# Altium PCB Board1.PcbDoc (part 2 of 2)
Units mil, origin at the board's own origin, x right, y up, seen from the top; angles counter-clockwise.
Board outline 6000 x 4000 mil, 8 copper layers (Top Layer, 3.3V, 2.5V, 1.8V, 1.0V, GND, signal2, Bottom Layer), stack 66.302 mil thick; 90 components, 131 nets, 720 pads, 306 vias.
Unrouted connection lines stored in the file: 162.
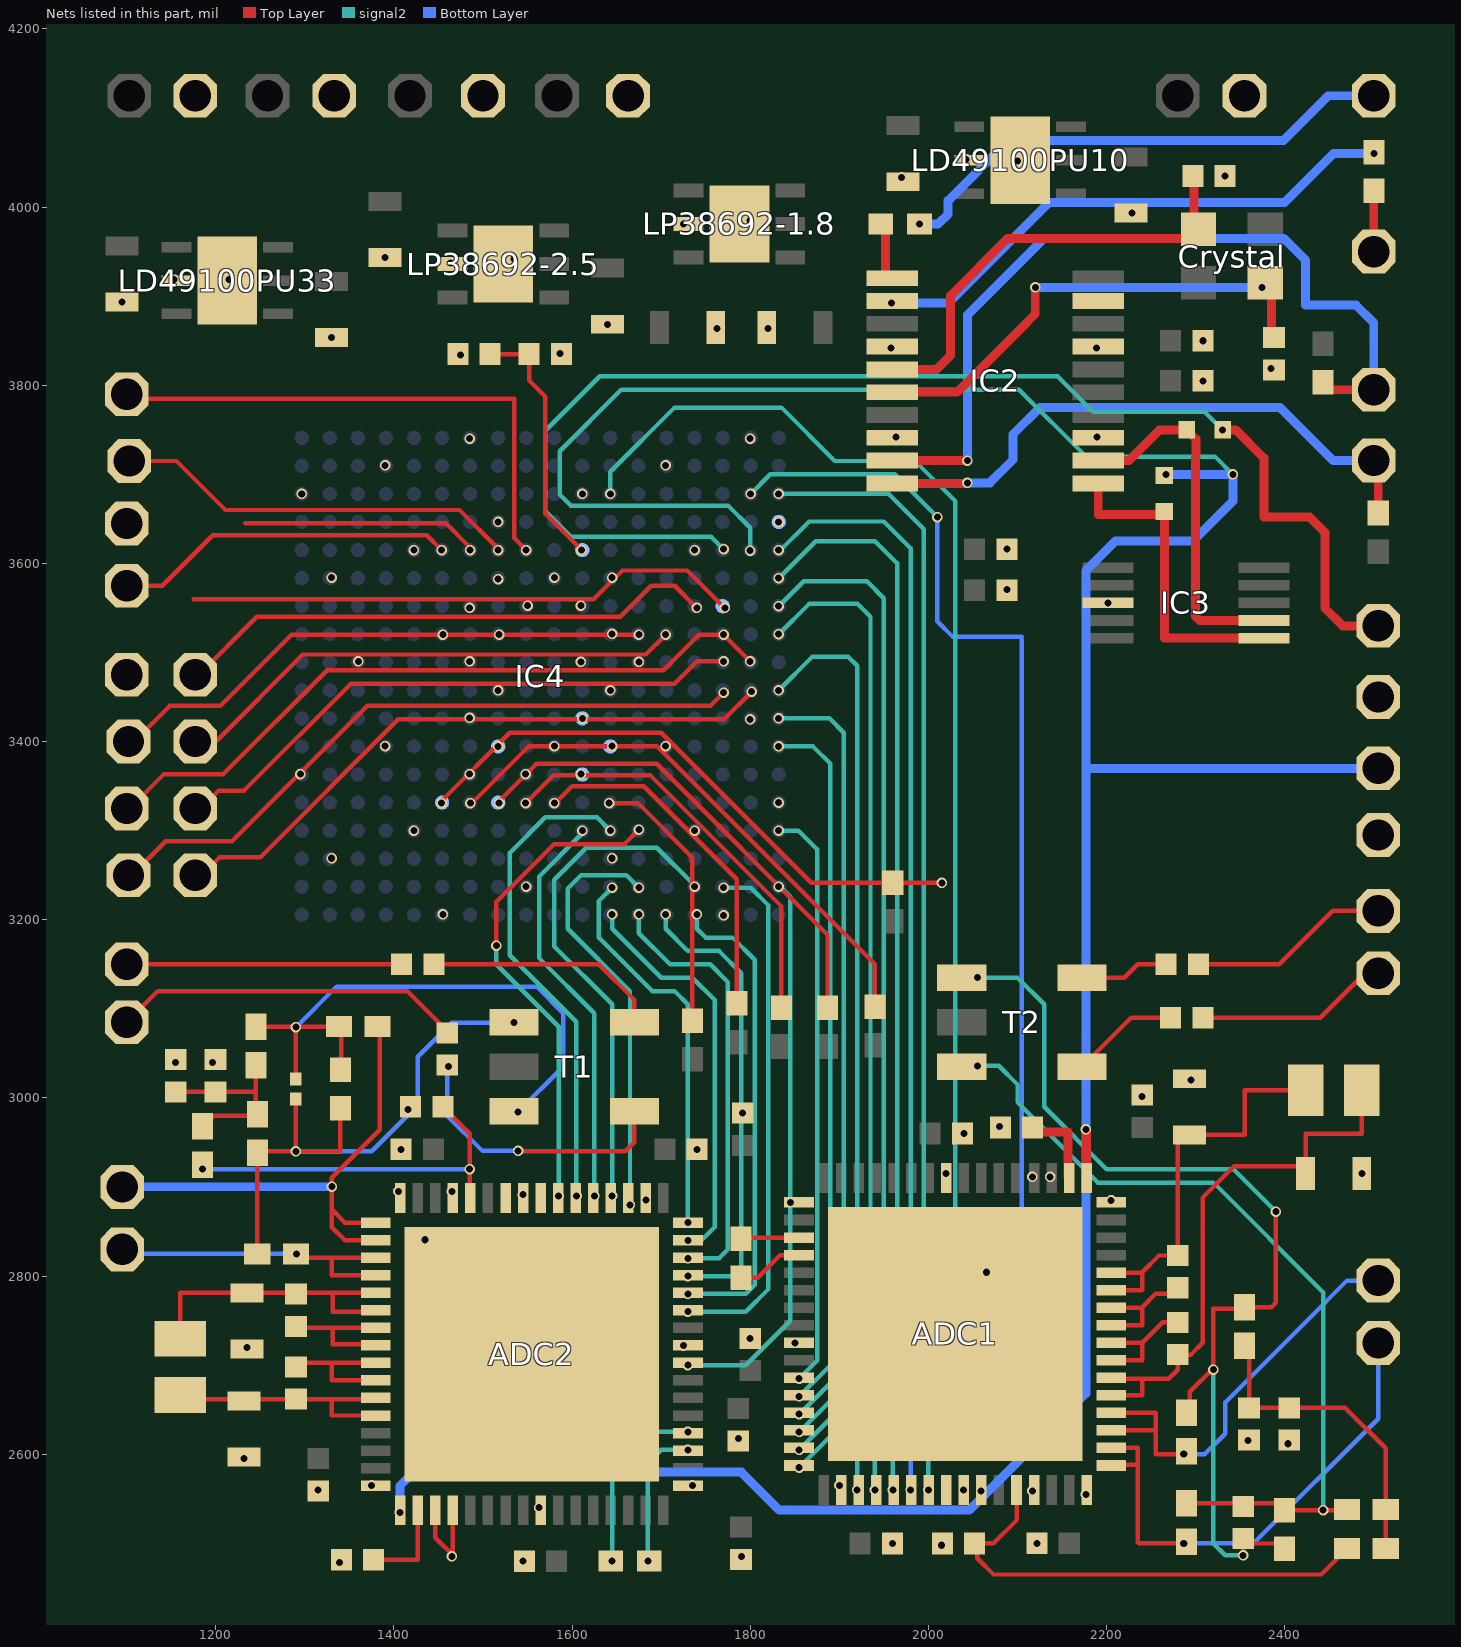
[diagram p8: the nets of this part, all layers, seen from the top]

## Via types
v1: diameter 11.81, hole 7.87, Top Layer to GND, 77 vias
v2: diameter 11.81, hole 7.87, Top Layer to Bottom Layer, 50 vias
v3: diameter 11.81, hole 7.87, GND to Bottom Layer, 47 vias
v4: diameter 11.81, hole 7.87, Top Layer to signal2, 33 vias
v5: diameter 11.81, hole 7.87, 3.3V to Bottom Layer, 27 vias
v6: diameter 11.81, hole 7.87, signal2 to Bottom Layer, 25 vias
v7: diameter 11.81, hole 7.87, Top Layer to 2.5V, 17 vias
v8: diameter 11.81, hole 7.87, 1.0V to Bottom Layer, 16 vias
v9: diameter 11.81, hole 7.87, Top Layer to 3.3V, 10 vias
v10: diameter 11.81, hole 7.87, 1.8V to Bottom Layer, 4 vias

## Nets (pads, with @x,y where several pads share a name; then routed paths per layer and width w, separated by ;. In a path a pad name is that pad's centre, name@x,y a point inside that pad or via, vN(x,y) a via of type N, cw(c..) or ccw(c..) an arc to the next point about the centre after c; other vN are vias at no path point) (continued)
ADC1_1: ADC1.43 | length 654.1
  signal2 w5: v6(1831.97,3300.08) 1854.09,3300.08 1875,3279.17 1875,2705 v4(1855,2685)
ADC1_2: ADC1.44 | length 790.6
  signal2 w5: v6(1831.97,3394.57) 1870.43,3394.57 1890,3375 1890,2700 v4(1855,2665)
ADC1_3: ADC1.45 | length 865.4
  signal2 w5: v6(1831.97,3426.06) 1888.94,3426.06 1905,3410 1905,2695 v4(1855,2645)
ADC1_4: ADC1.46 | length 994.6
  signal2 w5: v6(1831.97,3457.56) 1869.41,3495 1910,3495 1920,3485 1920,2690 v4(1855,2625)
ADC1_5: ADC1.47 | length 1091.7
  signal2 w5: v6(1831.97,3520.55) 1866.42,3555 1920,3555 1935,3540 1935,2685 v4(1855,2605)
ADC1_6: ADC1.48 | length 1152.8
  signal2 w5: v6(1831.97,3552.05) 1859.92,3580 1930.98,3580 1950,3560.98 1950,2680 v4(1855,2585)
ADC1_7: ADC1.51 | length 1219.2
  signal2 w5: v6(1831.97,3583.54) 1873.43,3625 1940,3625 1965,3600 1965,2675 1920,2630 v4(1920,2560)
ADC1_8: ADC1.52 | length 1247.4
  signal2 w5: v6(1831.97,3615.04) 1834.06,3615.04 1866.1,3647.09 1950,3647.09 1980,3617.09 1980,2670 1940,2630 v4(1940,2560)
ADC1_9: ADC1.53 | length 1272.4
  signal2 w5: v6(1831.97,3678.03) 1955.47,3678.03 1995,3638.5 1995,2665 1960,2630 v4(1960,2560)
ADC1_10: ADC1.54 | length 1464.6
  signal2 w5: v6(1800.47,3678.03) 1822.44,3700 1962.09,3700 v2(2010,3652.09)
  Bottom Layer w5: v2(1980,2560) 1980,2620 2105,2745 2105,3515 ; v2(2010,3652.09) 2010,3535 2027.52,3517.48 2105,3517.48
ADC1_11: ADC1.55 | length 1607.7
  signal2 w5: v6(1642.99,3678.03) 1642.99,3702.99 1715,3775 1835,3775 1895,3715 1985,3715 2030,3670 2030,2645 2000,2615 v4(2000,2560)
ADC2_0: ADC2.40 | length 629.3
  signal2 w5: v4(1730,2700) 1795,2700 1845,2750 1845,3225.98 1833.9,3237.09 v6(1831.97,3237.09)
ADC2_1: ADC2.43 | length 590
  signal2 w5: v4(1730,2760) 1795,2760 1820,2785 1820,3216.57 1800.59,3235.98 v6(1770,3235.98)
ADC2_2: ADC2.44 | length 539.7
  signal2 w5: v4(1730,2780) 1795,2780 1805,2790 1805,3155 1780,3180 1750,3180 1740,3190 v6(1740,3206.06)
ADC2_3: ADC2.45 | length 518.7
  signal2 w5: v6(1705,3206.06) 1705,3190 1730,3165 1765,3165 1790,3140 1790,2804.65 1785.35,2800 ; v4(1730,2800) 1785,2800
ADC2_4: ADC2.46 | length 493
  signal2 w5: v6(1675,3206.06) 1675,3185 1710,3150 1755,3150 1775,3130 1775,2830 1765,2820 v4(1730,2820)
ADC2_5: ADC2.47 | length 455.4
  signal2 w5: v6(1645,3206.06) 1645,3190 1700,3135 1735,3135 1760,3110 1760,2855 1745,2840 v4(1730,2840)
ADC2_6: ADC2.48 | length 438.3
  signal2 w5: v6(1645,3236.06) 1630,3221.06 1630,3180 1690,3120 1715,3120 1730,3105 v4(1730,2860)
ADC2_7: ADC2.51 | length 476
  signal2 w5: v4(1665,2880) 1665,3120 1595,3190 1595,3235 1610,3250 1661.06,3250 v6(1675,3236.06)
ADC2_8: ADC2.52 | length 573.4
  signal2 w5: v4(1645,2890) 1645,3105 1580,3170 1580,3245 1615.98,3280.98 1695.08,3280.98 1737.48,3238.58 v6(1737.48,3237.09)
ADC2_9: ADC2.53 | length 455.9
  signal2 w5: v6(1611.5,3300.08) 1611.5,3296.97 1562.95,3248.43 1562.95,3157.05 1625,3095 v4(1625,2890)
ADC2_10: ADC2.54 | length 554.6
  signal2 w5: v4@1604.53,2890 1604.53,3085.47 1530,3160 1530,3275 1570,3315 1628.07,3315 v6(1642.99,3300.08) v6@1642.99,3303.07
  other v4: 1605,2890
ADC2_11: ADC2.55 | length 552.6
  Top Layer w5: v2(1515,3171.06) 1515,3220 1580,3285 1658.94,3285 v2(1675,3301.06)
  signal2 w5: v2(1515,3171.06) 1515,3150 1585,3080 v4(1585,2890)
C1_1: C1.1 T2.5 | length 126
  Top Layer w5: T2.5@2172.52,3035 2227.52,3090 C1.1@2275.77,3090
C1_2: C1.2 pad.0@2505,3140 | length 202.6
  Top Layer w5: C1.2@2308.11,3090 2440,3090 pad.0@2490,3140
C2_1: C2.1 T2.4 | length 93.1
  Top Layer w5: T2.4@2185,3135 2220,3135 2235,3150 C2.1@2271.89,3150
C2_2: 
C65_1: ADC1.60 C65.1@2051.89,2499.8 R_new2.2 | length 530.5
  Top Layer w5: ADC1.60@2099.37,2550 2099.37,2526.26 2073.11,2500 2054.92,2500 2054.92,2483.19 2073.11,2465 2440.98,2465 R_new2.2@2469.96,2493.98
Clock1: ADC1.17 ADC2.17 pad.0@2505,3370 R32.2 | length 3609.8
  Top Layer w10: ADC1.17@2177.64,2910.2 v2@2177.64,2961.89
  signal2 w5: v6(1800,3614.49) 1800,3640.08 1775.08,3665 1598.5,3665 1586.06,3677.44 1586.06,3726.06 1655,3795 2101.81,3795 2176.81,3720 2321.73,3720 v2(2341.81,3699.92)
  Bottom Layer w10: v2(1406.81,2534.76) 1406.81,2564.41 1422.4,2580 1790,2580 1832.72,2537.28 2045.91,2537.28 2176.81,2668.19 v2(2176.81,2964.76) 2176.81,3370 ; v2(2266.81,3699.92) v2(2341.81,3699.92) 2341.81,3670 2300,3628.19 ; 2300,3625 2210,3625 2176.81,3591.81 2176.81,3370 ; pad.0@2505,3370 2176.81,3370
Clock2: pad.0@2505,3530 R31.2 | length 1472.8
  Top Layer w10: R31.2@2330.32,3750 2345,3750 2376.65,3718.35 2376.65,3652.09 2427.91,3652.09 2445,3635 2445,3550 2465,3530 pad.0@2505,3530
  signal2 w5: v6(1770,3615.98) 1755.98,3630 1598.5,3630 1570,3658.5 1570,3748.94 1631.06,3810 2145,3810 2185,3770 2310.08,3770 v2(2330.16,3749.92)
DONE: R41.2 | length 475.1
  Top Layer w5: v2@1547.95,3331.06 1579.37,3362.48 1687.52,3362.48 1835,3215 R41.2@1835,3101.05
  other v2: 1547.95,3330.98
GND: ADC1.16 ADC1.25 ADC1.33 ADC1.41 ADC1.50 ADC1.57 ADC1.58 ADC1.61 ADC1.64 ADC1.65 ADC2.16 ADC2.19 ADC2.20 ADC2.25 ADC2.33 ADC2.41 ADC2.50 ADC2.57 ADC2.58 ADC2.61 ADC2.64 ADC2.65 C2.2 C3.1 C4.1 C7.1 C8.2 C17.1 C18.1 C19.2 C20.1 C21.1 C22.1 C24.1 C25.1 C26.1 C29.1 C31.2 C33.1 C39.1 C40.1 C41.2 C42.1 C43.1 C48.2 C50.2 C52.1 C53.1 C54.1 C56.2 C57.1@1971.5,4028.5 C58.1 C59.1 C60.1 C61.1 C62.1 C63.2 C64.1 C65.1@1471.89,3835 C65.2@2015.67,2499.8 C66.1@1418.78,2990 C66.2@1588.11,3835 C67.1 C68.2 IC2.4 IC2.8 IC2.13 IC2.17 IC3.8 IC4.D1 IC4.L8 IC4.M7 IC4.M11 IC4.N8 LD49100PU10.2 LD49100PU10.7 LD49100PU33.2 LD49100PU33.7 LP38692-1.8.2 LP38692-1.8.7 LP38692-2.5.2 LP38692-2.5.7 pad.0@1100,3150 pad.0@1177.05,4125 pad.0@1332.95,4125 pad.0@1500,4125 pad.0@1662.95,4125 pad.0@2355,4125 pad.0@2505,3210 pad.0@2505,3295 pad.0@2505,3450 | length 643.5
  Top Layer w5: pad.0@1100,3150 C24.1@1407.17,3150 ; ADC2.19@1446.54,2537.17 1446.54,2506.14 1466.22,2486.46 ADC2.20@1466.22,2537.17 ; C2.2@2303.11,3150 2393.94,3150 2453.94,3210 pad.0@2505,3210
  other v1: 1339.13,2478.35 1545,2480 1465,2485.24 1790,2485 2014.65,2497.83 1959.53,2499.8 2121.89,2500 1562.95,2540 2176.81,2555 2059.21,2558.86 2116.78,2558.86 1315,2560 2039.53,2559.84 1375,2565 1735,2565 1900,2565 1231.73,2595 2403.74,2611.77 2358.74,2615.55 1786.57,2617.91 1235,2719.68 1725,2721.89 1850,2725 1800,2730 2065,2804.3 1435,2840.79 1845,2882.64 1682.91,2885.47 2205,2885 1544.65,2891.5 1405,2895 1465,2895 2116.78,2911.38 2136.78,2911.38 2020,2915 2486.5,2915 1407.99,2942.36 1740.43,2942.36 2040,2960 2080,2968.07 1791.57,2982.87 1415.63,2986.89 2240,3001.69 2295,3020 1155,3040 1196.5,3040 2015,3241.5 2201.46,3555.63 2088.11,3570.98 2088.11,3615.98 1963.74,3741.89 2189.39,3741.89 2308.11,3805 2384.8,3818.78 1475,3833.94 1586.5,3835.69 1957.76,3841.89 2188.74,3841.89 2308.11,3850 1330,3853.5 1762.91,3863.5 1820,3863.5 1640,3868.5 1095,3893.5 1153.39,3918.5 1215,3918.5 1463.5,3937.01 1535,3942.01 1389.96,3943.5 1725,3981.1 1800,3985 2228.62,3993.5 1970,4033.5 2333.11,4035 2100,4052.01 2042.48,4053.5
  other v3: 1770,3205 1455,3206.06 1548.5,3237.09 1330,3269.06 1645,3269.06 1422.52,3300.08 1737.48,3300.08 1831.97,3331.57 1295,3363.54 1485,3363.54 1547.95,3363.54 1610,3363.54 1390,3395 1517.01,3394.57 1580,3395 1645,3395.04 1705,3395 1800,3425 1611.5,3426.06 1485,3426.54 1517.01,3457.56 1642.99,3457.56 1360,3490 1485,3490 1610,3489.53 1675,3489.53 1455,3520 1518.03,3520 1770,3520 1645,3521.02 1485,3550 1550,3552.52 1610,3552.52 1517.01,3582.52 1330,3584.02 1580,3584.02 1645,3584.02 1422.52,3615.04 1737.48,3615.04 1517.01,3646.54 1831.97,3646.54 1296.54,3678.03 1611.5,3678.03 1390,3710 1705,3710 1485,3740 1800,3740
INIT: R39.2 | length 302.1
  Top Layer w5: v2(1641.5,3330.98) 1674.02,3330.98 1735,3270 R39.2@1735,3086.65
IO1: IC4.G3 pad.0@1100,3475 | length 627.3
  Top Layer w5: 1175,3560 1624.41,3560 1656.5,3592.09 1729.45,3592.09 v2(1771.54,3550)
IO2: pad.0@1177.05,3475 | length 612
  Top Layer w5: pad.0@1180,3473.98 1246.02,3540 1653.98,3540 1688.78,3574.8 1715.2,3574.8 v2(1740,3550)
IO3: pad.0@1102.05,3400 | length 628.2
  Top Layer w5: pad.0@1100,3391.61 1148.39,3440 1205,3440 1285,3520 v2(1675,3520)
IO4: pad.0@1177.05,3400 | length 569
  Top Layer w5: pad.0@1185,3401.61 1201.61,3401.61 1297.8,3497.8 1682.8,3497.8 v2(1705,3520)
IO5: pad.0@1100,3325 | length 787.5
  Top Layer w5: pad.0@1105,3326.61 1141.93,3363.54 1208.54,3363.54 1325,3480 1702.52,3480 1742.52,3520 1770,3520 v2(1800,3490)
IO6: pad.0@1177.05,3325 | length 659.7
  Top Layer w5: pad.0@1180,3321.61 1203.39,3345 1231.73,3345 1351.73,3465 1715,3465 1740,3490 v2(1770,3490)
IO7: pad.0@1102.05,3250 | length 744.5
  Top Layer w5: pad.0@1108.98,3253.39 1143.82,3288.23 1218.23,3288.23 1370,3440 1755,3440 v2(1770,3455)
IO8: pad.0@1177.05,3250 | length 712.2
  Top Layer w5: pad.0@1177.48,3243.39 1204.09,3270 1250,3270 1405,3425 1770.59,3425 v2(1801.57,3455.98)
M0: R43.2 | length 627.9
  Top Layer w5: v2@1487.56,3330.98 1551.57,3395 1695,3395 1940,3150 R43.2@1940,3102.55
  other v2: 1485.91,3330.98
M1: IC4.P13 R44.2 | length 664.8
  Top Layer w5: v2@1452.24,3332.24 1530,3410 1700,3410 1868.5,3241.5 R44.2@1960,3241.5 2015,3241.5
  other v2: 1453.5,3330.98
M2: IC4.P11 R42.2 | length 547.7
  Top Layer w5: v2@1518.03,3333.03 1560,3375 1695,3375 1886.73,3183.27 R42.2@1886.73,3101.05
  other v2: 1518.03,3330.98
NetADC1_1: ADC1.1 ADC1.2 pad.0@2505,2725 R6.2 | length 584.1
  Top Layer w5: ADC1.2@2205.2,2607.05 2235,2607.05 2235,2588.35 ; ADC1.1@2206.18,2588.35 2235,2588.35 ; 2235,2501.34 2235,2588.35 ; 2236.28,2500.06 R6.2@2290,2500.06
  Top Layer w10: v2(2286.65,2500) R6.2@2290,2503.35
  Bottom Layer w5: v2(2286.65,2500) 2365,2500 2505,2640 pad.0@2505,2725
NetADC1_3: ADC1.3 ADC1.4 pad.0@2505,2795 R7.2 | length 497.1
  Top Layer w5: ADC1.3@2205.2,2626.73 2255,2626.73 ; ADC1.4@2205.2,2646.42 2254.76,2646.42 ; 2255,2646.42 2255,2600 v2(2286.65,2600)
  Bottom Layer w5: v2(2286.65,2600) 2310,2600 2333.11,2623.11 2333.11,2658.11 2425,2750 2470,2795 pad.0@2505,2795
NetADC1_5: ADC1.5 ADC1.6 C5.2 C7.2 C9.2 | length 623.5
  Top Layer w5: ADC1.5@2205.2,2666.1 2240,2666.1 2240,2684.76 ADC1.6@2206.22,2684.76 ; 2239.53,2684.76 2269.76,2684.76 2280,2695 C5.2@2280,2711.89 2294.83,2711.89 2308.1,2725.16 2308.1,2888.1 2343.5,2923.5 2423.5,2923.5 2423.5,2960 2486.5,2960 C9.2@2486.5,3008.54
NetADC1_7: ADC1.7 ADC1.8 C5.1 | length 138.6
  Top Layer w5: ADC1.7@2205.2,2705.47 2240,2705.47 2240,2725.16 ADC1.8@2205.2,2725.16 ; 2240.16,2725.16 2263.11,2748.11 C5.1@2280,2748.11
NetADC1_9: ADC1.9 ADC1.10 C6.2 | length 129.2
  Top Layer w5: ADC1.9@2205.2,2744.84 2239.84,2744.84 ; ADC1.10@2205.2,2764.53 2239.53,2764.53 ; 2240,2745 2240,2764.06 ; 2240,2765 2255,2780 C6.2@2275,2780
NetADC1_11: ADC1.11 ADC1.12 C6.1 C8.1 C9.1 | length 458.5
  Top Layer w5: ADC1.11@2205.2,2784.21 2239.68,2784.21 ; ADC1.12@2205.2,2803.9 2239.84,2803.9 2239.84,2784.37 ; 2240,2804.3 2258.81,2823.11 C6.1@2280,2823.11 C8.1@2280,2965 ; C8.1@2293.35,2958.5 2355,2958.5 2355,3008.54 C9.1@2423.5,3008.54
NetADC1_13: 
NetADC1_17: 
NetADC1_18: ADC1.18 C67.2 | length 87.1
  Top Layer w10: C67.2@2119.61,2961.89 2156.5,2961.89 ADC1.18@2156.5,2911.65
NetADC1_55: 
NetADC1_56: ADC1.56
NetADC2_1: ADC2.1 ADC2.2 pad.0@1095,2900 R17.2 | length 614.1
  Top Layer w5: ADC2.2@1379.61,2840.32 1345.32,2839.98 1330.29,2854.72 ; ADC2.1@1379.61,2860 1345,2860 1330.1,2874.9 1330.29,2854.72 ; R17.2@1384.13,3080 1384.13,2964.13 1330.29,2910.29 v2(1330.29,2900.29) 1330.29,2854.72
  Bottom Layer w10: pad.0@1095,2900 v2(1330.29,2900.29)
NetADC2_3: ADC2.3 ADC2.4 pad.0@1095,2830 R18.2 | length 344.8
  Top Layer w5: R18.2@1294.37,2820.63 ADC2.3@1379.61,2820.63 ; 1330,2820.63 1330,2801.14 ADC2.4@1379.41,2801.14
  Bottom Layer w5: pad.0@1100,2825 v2(1290.63,2825)
NetADC2_5: ADC2.5 ADC2.6 C28.2 C29.2 C30.2 | length 339.3
  Top Layer w5: C28.2@1160,2729.61 1160,2781.26 ADC2.5@1379.61,2781.26 ; 1331.26,2781.26 1331.26,2760 ADC2.6@1378.03,2760
NetADC2_7: ADC2.7 ADC2.8 C30.1 | length 155.5
  Top Layer w5: C30.1@1290,2741.89 ADC2.7@1379.61,2741.89 ; 1331.26,2741.89 1331.26,2723.27 ADC2.8@1378.54,2723.27
NetADC2_9: ADC2.9 ADC2.10 C32.2 | length 154.5
  Top Layer w5: C32.2@1294.41,2702.52 ADC2.9@1379.61,2702.52 ; 1330,2702.52 1330,2682.83 ADC2.10@1379.61,2682.83
NetADC2_11: ADC2.11 ADC2.12 C28.1 C31.1 C32.1 | length 274.5
  Top Layer w5: C28.1@1171.89,2661.89 C32.1@1290,2661.89 ADC2.11@1378.35,2661.89 ; 1330,2661.89 1330,2643.46 ADC2.12@1379.61,2643.46
NetADC2_17: 
NetADC2_18: ADC2.18 C68.1 | length 105.3
  Top Layer w5: C68.1@1377.24,2481.46 1426.85,2481.46 ADC2.18@1426.85,2537.17
NetADC2_55: 
NetADC2_56: ADC2.56
NetC1_2: 
NetC2_1: 
NetC2_2: 
NetC3_1: 
NetC3_2: C3.2 C4.2 R1.1 R2.2 R_new2.1 | length 351.6
  Top Layer w5: R2.2@2360,2718.78 C4.2@2360,2651.97 2468.03,2651.97 2513.27,2606.73 R_new2.1@2513.27,2493.98
NetC10_1: 
NetC11_2: 
NetC12_2: 
NetC13_1: C13.1 R2.1 R5.1 R7.1 T2.3 | length 1114.7
  Top Layer w5: R7.1@2293.35,2650 2293.35,2670.01 2320,2696.66 2320,2763.11 R2.1@2352.99,2763.11 ; v4(2353.35,2486.46) C13.1@2353.35,2505.16 ; R2.1@2355,2765.12 2385.12,2765.12 2390,2770 v4(2390,2872.4) ; C13.1@2360,2499.8 2405.82,2499.8 R5.1@2400,2493.98
  signal2 w5: v4(2055,3135) 2100,3135 2130,3105 2130,2990 2200,2920 2342.4,2920 v4(2390,2872.4) ; v4(2320,2695) 2320,2499.57 2333.11,2486.46 v4(2353.35,2486.46)
NetC13_2: C13.2 R1.2 R5.2 R6.1 T2.1 | length 925.8
  Top Layer w5: R6.1@2290.86,2544.93 2392.36,2544.93 R5.2@2399.17,2538.11 ; R5.2@2400,2537.28 R1.2@2465,2537.28
  signal2 w5: v4(2055,3036.02) 2078.98,3036.02 2100,3015 2100,2995 2190,2905 2320,2905 2443.03,2781.97 v4(2443.03,2537.28)
NetC14_1: 
NetC14_2: 
NetC15_2: 
NetC23_1: C23.2 pad.0@1100,3085 | length 391
  Top Layer w5: pad.0@1100,3085 1135,3120 1415,3120 C23.2@1458.5,3076.5
NetC23_2: C23.1 T1.5 | length 320.3
  Top Layer w5: v2@1539.4,2940 1659.61,2940 1670,2950.39 T1.5@1670,2985
  Bottom Layer w5: v2@1460,3035 1460,2980 1499.54,2940.46 v2(1539.4,2940.46)
  other v2: 1461.45,3035.46
NetC24_1: 
NetC24_2: C24.2 T1.4 | length 266.6
  Top Layer w5: C24.2@1444.96,3150 1630,3150 1670,3110 T1.4@1670,3085
NetC25_2: C25.2 C26.2 R14.1 R15.2 R_new1.2 | length 208.2
  Top Layer w5: C26.2@1155,3006.89 1243.11,3006.89 ; R_new1.2@1186.42,2968.31 1198.11,2980 1245,2980 R14.1@1245,3036.69
NetC27_1: 
NetC34_2: 
NetC35_2: 
NetC36_1: 
NetC36_2: 
NetC37_2: 
NetC44_2: 
NetC47_2: 
NetC48_2: 
NetC52_2: C52.2 Crystal.1@2303.11,3975 IC2.5 | length 512.9
  Top Layer w10: IC2.5@1959.33,3817.8 2009.29,3817.8 2025,3833.5 2025,3900.71 2089.29,3965 Crystal.1@2308.11,3965 ; Crystal.1@2298.11,3970 C52.2@2298.11,4033.78
NetC53_2: C53.2 Crystal.1@2378.11,3915 IC2.6 | length 527.8
  Top Layer w10: IC2.6@1959.33,3792.2 2032.2,3792.2 2101.75,3861.75 2120,3880 v2(2120,3910) ; C53.2@2385,3853.5 Crystal.1@2385,3899.25
  Bottom Layer w10: v2(2120,3910) v2@2375,3910
  other v2: 2374.33,3909.92
NetC57_1: C57.1@1290,2998.9 R15.1 R16.1 R18.1 T1.3 | length 651.3
  Top Layer w5: R18.1@1246.69,2825 R15.1@1246.69,2938.35 1248.35,2940 1340,2940 R16.1@1340,2988.35 ; v2(1290,2940) C57.1@1290,2998.9
  Bottom Layer w5: v2(1290,2940) 1375,2940 1426.85,2991.85 1426.85,3046.25 1465,3084.4 v2(1535,3084.4)
NetC57_2: C57.2@1290,3021.1 R14.2 R16.2 R17.1 T1.1 | length 662.6
  Top Layer w5: R14.2@1245,3080 R17.1@1338.35,3080 ; C57.2@1290,3021.1 v2@1290,3080 ; R16.2@1340.83,3032.48 R17.1@1340.83,3080
  Bottom Layer w5: v2(1290,3079.4) 1335.6,3125 1560,3125 1590,3095 1590,3035 v2(1539.4,2984.4)
NetC66_2: ADC2.60 C66.2@1455,2990 R_new1.1 | length 414
  Top Layer w5: C66.2@1455,2990 1485,2960 ADC2.60@1485,2888.46
  Bottom Layer w5: v2(1185,2920) v2(1485,2920)
NetIC1_3: 
NetIC1_8: 
NetIC2_1: 
NetIC2_2: 
NetIC2_6: 
NetIC2_11: IC2.11 IC3.1 R32.1 | length 349.4
  Top Layer w10: IC2.11@2190.67,3689.84 2190.67,3655 R32.1@2259.76,3655 ; R32.1@2264.84,3649.92 2264.84,3516.26 IC3.1@2376.65,3516.26
NetIC2_12: IC2.12 IC3.2 R31.1 | length 405.1
  Top Layer w10: IC2.12@2190.67,3715.43 2225,3715.43 2259.57,3750 R31.1@2290,3750 2300.32,3739.68 2300.32,3720 ; 2300,3540.63 2300,3719.68 ; 2300.32,3540.32 2304.69,3535.94 IC3.2@2376.65,3535.94
NetIC2_19: IC2.19
NetR3_1: 
NetR4_2: 
NetR20_1: 
NetR32_2: 
PROGRAMB: R40.2 | length 394
  Top Layer w5: v2@1580.98,3330.98 1600,3350 1680.51,3350 1785,3245.51 R40.2@1785,3106.65
  other v2: 1580,3330.98
R33_1: ADC1.35 R33.1 | length 63.8
  Top Layer w5: R33.1@1791.01,2843.27 ADC1.35@1854.8,2843.27
R33_2: ADC1.36 R33.2 | length 79.3
  Top Layer w5: R33.2@1786.01,2798.27 1808.27,2798.27 1833.58,2823.58 ADC1.36@1854.8,2823.58
R34_2: ADC2.36 R34.2 | length 207.9
  signal2 w5: v4(1645,2480) 1645,2587.2 1682.8,2625 v4(1730,2625)
R34_!: ADC2.35 R34.1 | length 161.2
  signal2 w5: v4(1685,2480) 1685,2590 1700,2605 v4(1730,2605)
S1A1: IC2.2 R36.1 | length 610.8
  Bottom Layer w10: v2(1958.74,3892.21) 2022.21,3892.21 2135,4005 2399.57,4005 2454.57,4060 v2(2500,4060)
S1A11: pad.0@2500,3950 R36.2 | length 68.3
  Top Layer w10: pad.0@2500,3950 R36.2@2500,4018.35
SCLOCK: IC2.10 pad.0@2500,3715.43 R37.1 | length 669.9
  Top Layer w10: IC2.10@1959.33,3689.84 v2@2043.15,3689.84 ; R37.1@2505,3656.65 pad.0@2505,3710
  Bottom Layer w10: v2(2043.74,3690.43) 2069.02,3690.43 2095,3716.42 2095,3745 2125,3775 2395,3775 2454.57,3715.43 pad.0@2500,3715.43
SDATA': IC2.9 pad.0@2500,3795 R38.1 | length 940.2
  Top Layer w10: IC2.9@1959.33,3715.43 v2(2043.74,3715.43) ; R38.1@2443.03,3795 pad.0@2500,3795
  Bottom Layer w10: v2(2043.74,3715.43) 2043.74,3878.74 2130,3965 2398.7,3965 2423.5,3940.2 2423.5,3890.2 ; 2423.5,3890 2480,3890 2500,3870 pad.0@2500,3795
SEL: IC2.1 R35.1 | length 55.4
  Top Layer w10: R35.1@1946.69,3981.1 1951.69,3976.1 IC2.1@1951.69,3927.8
SEL1: pad.0@2500,4125 R35.2 | length 578.4
  Bottom Layer w10: v2(1990,3981.1) 2011.1,3981.1 2022.21,3992.21 2022.21,4007.21 2090,4075 2398.74,4075 2448.74,4125 pad.0@2500,4125
TCK: pad.0@1100,3790 | length 607.6
  Top Layer w5: pad.0@1102.95,3785 1535,3785 1535,3628.5 v2(1548.5,3615)
TDI: pad.0@1102.95,3715 | length 456.3
  Top Layer w5: pad.0@1102.95,3715 1155.83,3715 1210.83,3660 1473.5,3660 1517.01,3616.5 v2(1517.01,3615.04)
TDO: pad.0@1100,3575 | length 383.7
  Top Layer w5: pad.0@1100,3575 1140,3575 1196.5,3631.5 1437.01,3631.5 v2(1453.5,3615)
TMS: pad.0@1100,3645 | length 266.7
  Top Layer w5: 1232.91,3645 1458.5,3645 1485.51,3617.99 v2(1485.51,3615.04)
VCCBATT: C65.2@1508.11,3835 C66.1@1551.89,3835 IC4.E8 | length 287.6
  Top Layer w5: C65.2@1508.11,3835 C66.1@1551.89,3835 1551.89,3805.43 1570,3787.32 1570,3655.98 v2@1610.55,3615.43
  other v2: 1610.55,3615
pads on no net: ADC1.19 ADC1.20 ADC1.21 ADC1.22 ADC1.23 ADC1.24 ADC1.27 ADC1.28 ADC1.29 ADC1.30 ADC1.31 ADC1.32 ADC1.37 ADC1.38 ADC1.39 ADC2.21 ADC2.22 ADC2.23 ADC2.24 ADC2.27 ADC2.28 ADC2.29 ADC2.30 ADC2.31 ADC2.32 ADC2.37 ADC2.38 ADC2.39 Crystal.1@2303.11,3915 Crystal.1@2378.11,3975 IC2.15 IC2.16 IC2.20 IC3.4 IC3.5 IC3.6 IC3.7 IC3.9 IC3.10 IC4.A1 IC4.A2 IC4.A3 IC4.A4 IC4.A5 IC4.A6 IC4.A7 IC4.A8 IC4.A9 IC4.A10 IC4.A11 IC4.A12 IC4.A13 IC4.A14 IC4.A15 IC4.A16 IC4.A17 IC4.A18 IC4.B1 IC4.B2 IC4.B3 IC4.B4 IC4.B5 IC4.B6 IC4.B7 IC4.B8 IC4.B9 IC4.B10 IC4.B11 IC4.B12 IC4.B13 IC4.B14 IC4.B15 IC4.B16 IC4.B17 IC4.B18 IC4.C1 IC4.C2 IC4.C3 IC4.C4 IC4.C5 IC4.C6 IC4.C7 IC4.C8 IC4.C9 IC4.C10 IC4.C11 IC4.C12 IC4.C13 IC4.C14 IC4.C15 IC4.C16 IC4.C17 IC4.C18 IC4.D2 IC4.D3 IC4.D4 IC4.D5 IC4.D6 IC4.D7 IC4.D8 IC4.D9 IC4.D10 IC4.D11 IC4.D12 IC4.D13 IC4.D14 IC4.D15 IC4.D16 IC4.D17 IC4.D18 IC4.E1 IC4.E2 IC4.E3 IC4.E4 IC4.E5 IC4.E6 IC4.E7 IC4.E9 IC4.E10 IC4.E11 IC4.E12 IC4.E13 IC4.E14 IC4.E15 IC4.E16 IC4.E17 IC4.E18 IC4.F1 IC4.F2 IC4.F3 IC4.F4 IC4.F5 IC4.F6 IC4.F7 IC4.F8 IC4.F9 IC4.F10 IC4.F11 IC4.F12 IC4.F13 IC4.F14 IC4.F15 IC4.F16 IC4.F17 IC4.F18 IC4.G1 IC4.G2 IC4.G4 IC4.G5 IC4.G6 IC4.G7 IC4.G8 IC4.G9 IC4.G10 IC4.G11 IC4.G12 IC4.G13 IC4.G14 IC4.G15 IC4.G16 IC4.G17 IC4.G18 IC4.H1 IC4.H2 IC4.H3 IC4.H4 IC4.H5 IC4.H6 IC4.H7 IC4.H8 IC4.H9 IC4.H10 IC4.H11 IC4.H12 IC4.H13 IC4.H14 IC4.H15 IC4.H16 IC4.H17 IC4.H18 IC4.J1 IC4.J2 IC4.J3 IC4.J4 IC4.J5 IC4.J6 IC4.J7 IC4.J8 IC4.J9 IC4.J10 IC4.J11 IC4.J12 IC4.J13 IC4.J14 IC4.J15 IC4.J16 IC4.J17 IC4.J18 IC4.K1 IC4.K2 IC4.K3 IC4.K4 IC4.K5 IC4.K6 IC4.K7 IC4.K8 IC4.K9 IC4.K10 IC4.K11 IC4.K12 IC4.K13 IC4.K14 IC4.K15 IC4.K16 IC4.K17 IC4.K18 IC4.L1 IC4.L2 IC4.L3 IC4.L4 IC4.L5 IC4.L6 IC4.L7 IC4.L9 IC4.L10 IC4.L11 IC4.L12 IC4.L13 IC4.L14 IC4.L15 IC4.L16 IC4.L17 IC4.L18 IC4.M1 IC4.M2 IC4.M3 IC4.M4 IC4.M5 IC4.M6 IC4.M8 IC4.M9 IC4.M10 IC4.M12 IC4.M13 IC4.M14 IC4.M15 IC4.M16 IC4.M17 IC4.M18 IC4.N1 IC4.N2 IC4.N3 IC4.N4 IC4.N5 IC4.N6 IC4.N7 IC4.N9 IC4.N10 IC4.N11 IC4.N12 IC4.N13 IC4.N14 IC4.N15 IC4.N16 IC4.N17 IC4.N18 IC4.P1 IC4.P2 IC4.P3 IC4.P4 IC4.P5 IC4.P6 IC4.P7 IC4.P8 IC4.P9 IC4.P10 IC4.P12 IC4.P14 IC4.P15 IC4.P16 IC4.P17 IC4.P18 IC4.R1 IC4.R2 IC4.R3 IC4.R4 IC4.R5 IC4.R6 IC4.R7 IC4.R8 IC4.R9 IC4.R10 IC4.R11 IC4.R12 IC4.R13 IC4.R14 IC4.R15 IC4.R16 IC4.R17 IC4.R18 IC4.T1 IC4.T2 IC4.T3 IC4.T4 IC4.T5 IC4.T6 IC4.T7 IC4.T8 IC4.T9 IC4.T10 IC4.T11 IC4.T12 IC4.T13 IC4.T14 IC4.T15 IC4.T16 IC4.T17 IC4.T18 IC4.U1 IC4.U2 IC4.U3 IC4.U4 IC4.U5 IC4.U6 IC4.U7 IC4.U8 IC4.U9 IC4.U10 IC4.U11 IC4.U12 IC4.U13 IC4.U14 IC4.U15 IC4.U16 IC4.U17 IC4.U18 IC4.V1 IC4.V2 IC4.V3 IC4.V4 IC4.V5 IC4.V6 IC4.V7 IC4.V8 IC4.V9 IC4.V10 IC4.V11 IC4.V12 IC4.V13 IC4.V14 IC4.V15 IC4.V16 IC4.V17 IC4.V18 LD49100PU10.3 LD49100PU33.3 T1.2 T2.2
copper on no net: | length 628.5
  Top Layer w5: 1100,3485 1175,3560 ; 1100,3645 1232.91,3645 ; 1290,2743.46 1300.32,2743.46 ; 2235,2501.34 2236.28,2500.06 ; 2239.53,2684.76 2240,2685.24
  Top Layer w10: 1095,3956.5 1154.33,3956.5 1155.83,3955 ; 1100,3475 1100,3485 ; 1102.95,4117.87 1102.95,4125 ; 1170,2660 1171.89,2661.89 ; 1185,2968.31 1186.42,2968.31 ; 1270,3955 1271.5,3956.5 ; 1325,3921.5 1328.9,3917.6 1330,3916.5 ; 1340,3031.65 1340.83,3032.48 ; 1377.24,2481.46 1382.28,2476.42 ; 1378.03,2760 1379.61,2761.57 ; 1378.54,2723.27 1379.61,2722.2 ; 1379.02,2603.5 1379.61,2604.09 ; 1379.41,2801.14 1379.61,2800.94 ; 1465.63,3898.5 1465.83,3898.7 ; 1473.5,4010 1475,4008.5 ; 1485.91,3330.98 1487.56,3330.98 ; 1518.03,3330.98 1518.03,3333.03 ; 1525.59,2976.89 1527.48,2975 ; 1547.95,3330.98 1547.95,3331.06 ; 1580,3330.98 1580.98,3330.98 ; 1580,3936.1 1636.1,3936.1 1640,3940 ; 1610.55,3615 1610.55,3615.43 ; 1695,3868.31 1698.31,3865 ; 1730.53,3943.41 1730.83,3943.7 ; 1789.4,2841.65 1791.01,2843.27 ; 1881.5,3865 1882.36,3865.87 ; 1914.92,3615.08 1915,3615 ; 1970,4091.5 1971.5,4090 ; 2000.47,2910.2 2001.89,2911.61 ; 2040,4095.83 2045.83,4090 ; 2043.15,3689.84 2043.74,3690.43 ; 2050.39,3568.5 2051.89,3570 ; 2156.5,2911.65 2157.95,2910.2 ; 2189.65,3870 2190.67,3868.98 ; 2205.2,2587.36 2206.18,2588.35 ; 2205.2,2685.79 2206.22,2684.76 ; 2223.62,4052.6 2227.52,4056.5 ; 2259.76,3655 2264.84,3649.92 ; 2272.52,4125 2280,4125 ; 2286.65,2600 2290,2603.35 ; 2290,2646.65 2293.35,2650 ; 2293.11,3965 2303.11,3975 ; 2296.89,4035 2298.11,4033.78 ; 2300,3719.68 2300.32,3720 ; 2352.99,2763.11 2355,2765.12 ; 2374.33,3909.92 2385,3899.25 ; 2399.17,2538.11 2400,2537.28 ; 2491.61,3365 2505,3378.39 ; 2505,3710 2510,3715 ; 1485,2888.46 1485.91,2887.56 1485,2888.46 ; 1951.69,3927.8 1959.33,3920.16 1951.69,3927.8 ; 1957.13,3790 1959.33,3792.2 1957.13,3790
  3.3V w10: 1535,2984.4 1539.4,2984.4
  Bottom Layer w10: 1095,2830 1100,2825 ; 1257.95,4122.05 1257.95,4125 ; 1582.95,4125 1585,4125 ; 2176.81,3380 2178.43,3378.39 ; 2300,3625 2300,3628.19 ; 2314.92,3699.92 2315,3700 ; 2491.61,3365 2505,3378.39 ; 2500,3510 2505,3515
  other v1: 1524.65,2891.5

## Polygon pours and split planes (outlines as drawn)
3.3V on 3.3V "3.3V_L02_P032" (solid, remove dead copper, pour order 32): 1055,4160 1055,2455 2545,2455 2545,4160
2.5V on 2.5V "2.5V_L03_P034" (solid, pour order 34): 1055,4160 1055,2455 2545,2455 2545,4160
1.8V on 1.8V "1.8V_L04_P036" (solid, pour order 36): 1055,4160 1055,2455 2545,2455 2545,4160
1.0V on 1.0V "1.0V_L05_P038" (solid, pour order 38): 1055,4160 1055,2455 2545,2455 2545,4160
GND on GND "GND_L06_P040" (solid, pour order 40): 1055,4160 1055,2455 2545,2455 2545,4160

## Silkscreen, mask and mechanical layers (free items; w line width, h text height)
Mechanical 13:
  lines w10: 1045,2445 2555,2445 2555,4175 1045,4175 1045,2445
